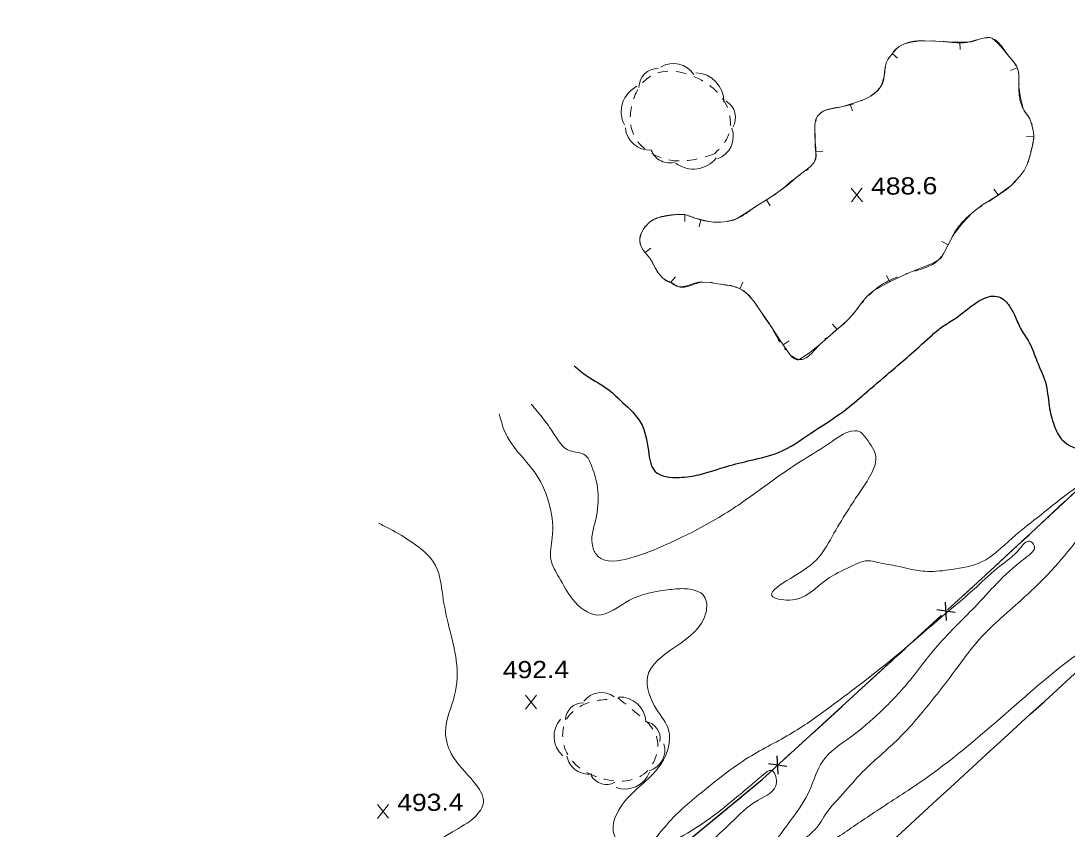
# Model space of a CAD drawing. Extents: x 2362213 to 2366494, y 6968794 to 6978110.
# Drawn here: x 2365880.2 to 2366171.9, y 6977341.8 to 6977567.2 of the extents above; entities that cross this region are included whole.
import ezdxf

# ---------------------------------------------------------------- set-up
doc = ezdxf.new("R2010")
doc.units = 0
doc.header["$LTSCALE"] = 1.9
for name, pattern in [('DOT_DASHED', [7.7, 5, -1.2, 0.3, -1.2]), ('LONG_DASH_SHORT_DASH', [9.9, 6, -1.2, 1.5, -1.2]), ('SHORT_DASHED', [2.7, 1.5, -1.2])]:
    doc.linetypes.add(name, pattern=pattern)
for name, color, linetype, lineweight in [('17', 7, 'Continuous', 25), ('2', 7, 'Continuous', 25), ('29', 7, 'Continuous', 13), ('31', 7, 'Continuous', 25), ('35', 7, 'Continuous', 13), ('37', 7, 'Continuous', 13)]:
    doc.layers.add(name, color=color, linetype=linetype, lineweight=lineweight)

msp = doc.modelspace()

# ---------------------------------------------------------------- linework, layer by layer
at = {"layer": '17'}
for p, q in [((2366140.674, 6977402.201), (2366135.606, 6977402.993)), ((2366138.314, 6977400.048), (2366137.975, 6977405.155)), ((2366092.575, 6977360.861), (2366136.841, 6977401.364)), ((2366091.391, 6977357.11), (2366091.042, 6977362.226)), ((2366093.75, 6977359.272), (2366088.681, 6977360.064))]:
    msp.add_line(p, q, dxfattribs=at)
at = {"layer": '17', "linetype": 'LONG_DASH_SHORT_DASH'}
msp.add_lwpolyline([(2365983.55, 6977264.148), (2366017.125, 6977295.339), (2366039.325, 6977316.401), (2366086.873, 6977355.657), (2366149.203, 6977412.683), (2366216.719, 6977475.439), (2366310.108, 6977562.092), (2366339.856, 6977586.717), (2366399.795, 6977631.2)], dxfattribs=at)
at = {"layer": '17'}
for points in [[(2366139.498, 6977403.8), (2366149.203, 6977412.683), (2366183.512, 6977444.571)], [(2366043.78, 6977320.084), (2366086.873, 6977355.657), (2366089.918, 6977358.436)]]:
    msp.add_lwpolyline(points, dxfattribs=at)
at = {"layer": '2'}
for points in [[(2365903.868, 6977136.953), (2366004.462, 6977229.375), (2366102.28, 6977319.291), (2366221.396, 6977428.431), (2366331.604, 6977527.895), (2366415.835, 6977603.96)], [(2366440.637, 6977561.845), (2366356.574, 6977485.121), (2366258.494, 6977395.293), (2366146.09, 6977293.258), (2366048.337, 6977203.972), (2365937.402, 6977102.032)]]:
    msp.add_spline(points, degree=3, dxfattribs=at)
at = {"layer": '29'}
for centre, radius, start, end in [((2366062.181, 6977548.703), 6.666, 32.06986, 122.06986), ((2366057.839, 6977548.637), 5.327, 89.3605, 179.3605), ((2366068.198, 6977544.775), 7.995, 358.55459, 88.55459), ((2366055.58, 6977541.86), 7.995, 116.95032, 206.95032), ((2366074.12, 6977540.307), 5.327, 329.08541, 59.08541), ((2366055.41, 6977537.869), 6.666, 184.26168, 274.26168), ((2366072.169, 6977535.049), 6.666, 289.80431, 19.80431), ((2366061.003, 6977532.969), 5.327, 199.27532, 289.27532), ((2366067.729, 6977533.893), 7.995, 232.39118, 322.39118), ((2366041.993, 6977373.864), 6.05, 53.36549, 143.36549), ((2366036.865, 6977372.204), 4.835, 88.09885, 178.09885), ((2366047.197, 6977371.422), 7.256, 3.13261, 93.13261), ((2366036.098, 6977367.728), 7.256, 138.79847, 228.79847), ((2366053.605, 6977367.054), 4.835, 350.69712, 80.69712), ((2366053.695, 6977363.928), 6.05, 286.12563, 16.12563), ((2366038.388, 6977363.234), 6.05, 189.70163, 279.70163), ((2366043.475, 6977359.107), 4.835, 208.93065, 298.93065), ((2366048.672, 6977360.262), 7.256, 249.60415, 339.60415)]:
    msp.add_arc(centre, radius, start, end, dxfattribs=at)
at = {"layer": '29', "linetype": 'SHORT_DASHED'}
for points in [[(2366073.711, 6977530.209), (2366063.66, 6977528.173), (2366051.1, 6977535.384), (2366055.684, 6977551.778), (2366069.966, 6977550.684), (2366077.652, 6977541.647), (2366077.247, 6977534.813), (2366073.67, 6977530.259)], [(2366046.635, 6977378.464), (2366052.117, 6977373.986), (2366057.459, 6977367.527), (2366054.503, 6977357.678), (2366042.199, 6977355.931), (2366032.073, 6977363.834), (2366032.145, 6977372.076), (2366037.361, 6977376.636), (2366045.618, 6977378.165)]]:
    msp.add_spline(points, degree=3, dxfattribs=at)
at = {"layer": '31', "lineweight": 13}
for p, q in [((2366114.842, 6977516.76), (2366111.725, 6977520.612)), ((2366111.762, 6977516.731), (2366114.805, 6977520.641)), ((2366023.984, 6977375.339), (2366020.866, 6977379.189)), ((2366020.903, 6977375.309), (2366023.947, 6977379.218)), ((2365982.701, 6977344.854), (2365979.586, 6977348.705)), ((2365979.623, 6977344.825), (2365982.665, 6977348.734))]:
    msp.add_line(p, q, dxfattribs=at)
at = {"layer": '31'}
msp.add_spline([(2366034.483, 6977470.993), (2366038.04, 6977468.167), (2366044.127, 6977464.324), (2366048.042, 6977460.751), (2366052.902, 6977455.388), (2366055.159, 6977447.289), (2366056.993, 6977441.646), (2366063.86, 6977439.911), (2366069.234, 6977440.662), (2366077.012, 6977442.967), (2366083.785, 6977444.701), (2366091.456, 6977446.874), (2366100.444, 6977452.24), (2366108.752, 6977457.769), (2366114.727, 6977462.607), (2366123.981, 6977470.515), (2366128.465, 6977474.368), (2366134.345, 6977479.714), (2366137.204, 6977481.981), (2366140.851, 6977484.356), (2366146.162, 6977488.367), (2366150.613, 6977490.42), (2366152.914, 6977490.271), (2366155.83, 6977487.719), (2366157.54, 6977484.615), (2366159.194, 6977480.961), (2366161.367, 6977477.512), (2366163.507, 6977472.312), (2366165.862, 6977466.474), (2366166.935, 6977459.834), (2366168.317, 6977454.408), (2366170.585, 6977450.358), (2366177.191, 6977447.731), (2366182.075, 6977449.557), (2366190.245, 6977454.696), (2366200.657, 6977463.025), (2366204.727, 6977468.354), (2366207.486, 6977473.72), (2366212.585, 6977483.179), (2366217.786, 6977488.279), (2366229.22, 6977496.428), (2366235.153, 6977500.226), (2366242.66, 6977504.807), (2366247.501, 6977505.873), (2366249.301, 6977502.751), (2366249.766, 6977500.145), (2366248.137, 6977495.868), (2366239.159, 6977484.962), (2366231.772, 6977475.262), (2366221.969, 6977465.028), (2366220.258, 6977462.931)], degree=3, dxfattribs=at)
at = {"layer": '35'}
for points in [[(2366022.463, 6977460.358), (2366025.842, 6977456.29), (2366028.63, 6977452.316), (2366033.238, 6977447.37), (2366037.55, 6977446.131), (2366039.277, 6977443.267), (2366041.075, 6977436.094), (2366040.461, 6977428.168), (2366039.624, 6977420.52), (2366041.209, 6977417.804), (2366049.864, 6977417.357), (2366060.307, 6977421.257), (2366066.41, 6977424.165), (2366079.568, 6977431.761), (2366090.307, 6977439.413), (2366097.579, 6977444.342), (2366106.476, 6977450.037), (2366112.679, 6977452.927), (2366113.61, 6977452.845), (2366115.94, 6977450.718), (2366118.579, 6977445.522), (2366116.842, 6977440.076), (2366113.905, 6977435.508), (2366111.115, 6977431.262), (2366106.9, 6977424.32), (2366102.694, 6977417.64), (2366094.77, 6977411.764), (2366089.586, 6977406.955), (2366094.468, 6977405.691), (2366104.923, 6977411.471), (2366111.58, 6977415.064), (2366117.105, 6977416.667), (2366119.379, 6977416.169), (2366124.628, 6977415.169), (2366127.896, 6977414.41), (2366132.993, 6977413.698), (2366139.809, 6977414.243), (2366148.088, 6977416.332), (2366156.576, 6977423.003), (2366163.553, 6977428.65), (2366172.386, 6977435.604), (2366178.929, 6977440.647), (2366182.262, 6977443.539), (2366187.4, 6977446.948), (2366191.377, 6977449.236), (2366191.966, 6977448.321), (2366189.019, 6977441.663), (2366187.804, 6977439.101), (2366181.754, 6977431.754), (2366173.753, 6977421.267), (2366166.611, 6977412.948), (2366159.012, 6977405.606), (2366146.87, 6977394.09), (2366140.806, 6977386.221), (2366133.9, 6977377.295), (2366124.312, 6977366.473), (2366115.619, 6977358.49), (2366110.085, 6977352.477), (2366104.488, 6977345.824), (2366100.963, 6977341.039), (2366098.119, 6977337.293), (2366098.478, 6977336.366), (2366101.937, 6977336.409), (2366108.653, 6977340.052), (2366118.859, 6977346.941), (2366131.439, 6977355.231), (2366149.435, 6977369.393), (2366161.616, 6977379.989), (2366180.529, 6977394.42), (2366186.358, 6977397.766), (2366199.886, 6977405.405), (2366210.622, 6977412.107), (2366220.878, 6977418.815), (2366228.477, 6977423.248), (2366233.166, 6977425.453), (2366236.793, 6977426.817), (2366243.377, 6977429.53), (2366250.655, 6977432.011), (2366253.973, 6977432.162), (2366257.463, 6977432.185), (2366262.578, 6977430.523), (2366264.282, 6977428.049), (2366266.206, 6977424.577), (2366266.382, 6977418.689), (2366264.391, 6977413.43), (2366261.413, 6977405.831), (2366257.476, 6977398.343), (2366250.572, 6977388.177), (2366240.063, 6977375.316), (2366229.503, 6977364.895), (2366218.841, 6977353.403), (2366209.693, 6977342.715), (2366198.055, 6977330.764), (2366188.256, 6977320.259), (2366178.313, 6977307.915), (2366164.632, 6977294.283), (2366152.223, 6977282.495)], [(2365880.182, 6977162.669), (2365882.691, 6977164.893), (2365887.056, 6977168.515), (2365893.475, 6977173.917), (2365899.091, 6977178.579), (2365905.489, 6977185.141), (2365908.161, 6977189.157), (2365913.006, 6977194.904), (2365917.148, 6977197.933), (2365920.521, 6977197.535), (2365923.026, 6977192.869), (2365926.023, 6977193.207), (2365932.717, 6977198.051), (2365944.859, 6977208.437), (2365955.882, 6977217.603), (2365970.594, 6977230.093), (2365976.985, 6977236.285), (2365987.668, 6977245.526), (2365998.863, 6977255.524), (2366009.515, 6977265.876), (2366012.174, 6977272.24), (2366014.106, 6977278.32), (2366019.63, 6977281.103), (2366022.297, 6977280.418), (2366024.586, 6977279.58), (2366027.021, 6977279.983), (2366029.101, 6977278.963), (2366033.795, 6977280.628), (2366037.91, 6977282.277), (2366041.745, 6977284.904), (2366048.493, 6977289.478), (2366053.623, 6977295.696), (2366061.627, 6977304.734), (2366066.032, 6977310.576), (2366068.335, 6977313.458), (2366075.422, 6977321.086), (2366080.862, 6977327.428), (2366088.806, 6977336.474), (2366095.327, 6977344.937), (2366100.093, 6977352.622), (2366103.765, 6977360.798), (2366111.543, 6977367.512), (2366119.776, 6977374.471), (2366128.21, 6977383.471), (2366135.069, 6977392.137), (2366146.158, 6977403.763), (2366160.23, 6977417.408), (2366162.746, 6977420.962), (2366161.505, 6977422.11), (2366158.675, 6977419.963), (2366153.179, 6977415.201), (2366146.615, 6977409.329), (2366137.937, 6977401.855), (2366125.933, 6977391.59), (2366117.509, 6977384.75), (2366106.089, 6977376.11), (2366095.291, 6977368.677), (2366083.164, 6977361.851), (2366069.889, 6977351.975), (2366059.639, 6977342.316), (2366051.152, 6977335.695), (2366045.722, 6977339.943), (2366048.59, 6977349.582), (2366058.71, 6977360.079), (2366060.791, 6977369.459), (2366057.415, 6977375.257), (2366054.919, 6977384.294), (2366071.191, 6977402.139), (2366070.747, 6977406.715), (2366065.256, 6977408.872), (2366060.528, 6977408.548), (2366049.915, 6977405.667), (2366040.855, 6977401.52), (2366034.053, 6977405.886), (2366030.284, 6977411.99), (2366027.957, 6977416.988), (2366028.359, 6977423.052), (2366027.706, 6977431.727), (2366023.892, 6977440.701), (2366015.463, 6977451.931), (2366013.538, 6977457.683)], [(2366152.223, 6977282.495), (2366137.48, 6977269.164), (2366127.401, 6977258.388), (2366118.523, 6977249.922), (2366117.96, 6977248.097), (2366119.044, 6977246.588), (2366121.484, 6977246.551), (2366126.773, 6977250.861), (2366140.883, 6977262.567), (2366156.737, 6977275.887), (2366174.131, 6977290.174), (2366190.688, 6977304.213), (2366211.305, 6977321.49), (2366231.204, 6977339.61), (2366246.965, 6977354.221), (2366270.092, 6977373.542), (2366286.124, 6977386.966), (2366306.411, 6977404.189), (2366319.943, 6977415.729), (2366336.838, 6977429.96), (2366354.441, 6977444.438), (2366361.918, 6977450.03), (2366367.772, 6977451.716), (2366372.313, 6977451.719), (2366373.898, 6977448.964), (2366372.614, 6977445.301), (2366369.195, 6977438.879), (2366363.214, 6977432.632), (2366354.604, 6977423.079), (2366342.302, 6977409.612), (2366327.29, 6977397.188), (2366311.288, 6977383.615), (2366289.667, 6977364.727), (2366279.323, 6977355.619), (2366272.319, 6977349.792), (2366258.434, 6977338.669), (2366245.681, 6977326.327), (2366235.563, 6977317.65), (2366218.37, 6977302.026), (2366206.626, 6977290.974), (2366190.041, 6977278.685), (2366181.707, 6977272.825), (2366173.374, 6977266.726), (2366161.242, 6977256.45), (2366147.282, 6977244.777), (2366139.539, 6977237.773), (2366132.064, 6977230.81), (2366121.213, 6977220.427), (2366111.765, 6977209.766), (2366107.156, 6977201.072), (2366105.674, 6977199.228)], [(2365979.938, 6977427.141), (2365983.063, 6977425.541), (2365989.229, 6977421.81), (2365995.831, 6977415.312), (2365997.791, 6977406.971), (2365999.554, 6977398.217), (2366001.595, 6977388.756), (2366001.127, 6977379.141), (2365998.583, 6977368.966), (2366000.201, 6977362.871), (2366006.617, 6977354.862), (2366009.15, 6977349.306), (2366006.908, 6977345.375), (2366000.508, 6977341.092), (2365985.993, 6977332.085), (2365981.742, 6977330.104), (2365977.662, 6977324.855), (2365975.538, 6977318.944), (2365976.625, 6977312.945), (2365973.435, 6977305.594), (2365967.146, 6977299.124), (2365965.894, 6977294.071), (2365969.263, 6977286.863), (2365971.693, 6977279.546), (2365966.079, 6977271.511), (2365961.628, 6977269.499), (2365957.289, 6977271.578), (2365952.849, 6977276.757), (2365949.5, 6977281.895), (2365947.552, 6977287.937), (2365944.719, 6977290.33), (2365940.726, 6977290.612), (2365932.588, 6977286.224), (2365925.314, 6977289.755), (2365919.493, 6977296.089), (2365911.156, 6977301.901), (2365903.542, 6977309.719), (2365892.542, 6977318.113), (2365882.657, 6977329.071)], [(2366044.302, 6977330.35), (2366047.549, 6977331.891), (2366056.184, 6977335.533), (2366065.001, 6977340.097), (2366073.12, 6977345.415), (2366079.214, 6977350.273), (2366083.431, 6977353.804), (2366087.161, 6977356.989), (2366089.42, 6977358.201), (2366090.852, 6977354.864), (2366085.778, 6977349.916), (2366078.168, 6977343.573), (2366071.963, 6977337.864), (2366067.242, 6977333.799)]]:
    msp.add_spline(points, degree=3, dxfattribs=at)
at = {"layer": '37'}
for p, q in [((2366142.048, 6977561.261), (2366142.087, 6977559.261)), ((2366123.147, 6977558.121), (2366124.65, 6977556.805)), ((2366157.967, 6977554.172), (2366156.124, 6977553.405)), ((2366111.412, 6977544.02), (2366112.03, 6977542.115)), ((2366162.619, 6977535.066), (2366160.62, 6977534.977)), ((2366101.857, 6977530.687), (2366103.845, 6977530.906)), ((2366152.694, 6977518.691), (2366151.518, 6977520.311)), ((2366088.074, 6977517.325), (2366089.121, 6977515.625)), ((2366065.351, 6977513.279), (2366065.36, 6977511.279)), ((2366069.797, 6977511.791), (2366069.295, 6977509.846)), ((2366138.746, 6977504.827), (2366136.977, 6977505.75)), ((2366054.272, 6977502.623), (2366055.841, 6977503.868)), ((2366122.483, 6977494.462), (2366121.516, 6977496.213)), ((2366061.411, 6977494.38), (2366062.747, 6977495.863)), ((2366080.61, 6977492.533), (2366081.482, 6977494.341)), ((2366107.839, 6977481.202), (2366106.514, 6977482.699)), ((2366092.77, 6977476.879), (2366094.42, 6977478.005))]:
    msp.add_line(p, q, dxfattribs=at)
for points in [[(2366061.411, 6977494.38), (2366061.926, 6977493.925), (2366062.318, 6977493.629), (2366062.962, 6977493.275), (2366063.644, 6977493.082), (2366064.464, 6977493.039), (2366065.912, 6977493.313), (2366068.076, 6977494.054), (2366069.163, 6977494.334), (2366070.252, 6977494.405), (2366072.353, 6977494.235), (2366074.456, 6977493.945), (2366078.011, 6977493.418), (2366079.746, 6977492.955), (2366081.413, 6977492.151), (2366082.814, 6977491.064), (2366084.502, 6977489.13), (2366085.952, 6977487.014), (2366087.748, 6977484.361), (2366089.544, 6977481.708), (2366091.939, 6977478.111), (2366094.373, 6977474.503), (2366094.979, 6977473.769), (2366095.544, 6977473.254), (2366095.997, 6977472.949), (2366096.679, 6977472.695), (2366097.009, 6977472.688), (2366097.308, 6977472.791), (2366100.14, 6977474.718), (2366102.938, 6977477.016), (2366106.718, 6977480.211), (2366110.387, 6977483.456), (2366112.328, 6977485.565), (2366114.946, 6977489.03), (2366116.37, 6977490.633), (2366118.026, 6977491.999), (2366122.802, 6977494.635), (2366127.74, 6977496.932), (2366131.954, 6977498.623), (2366134.067, 6977499.493), (2366136.087, 6977500.583), (2366136.88, 6977501.24), (2366140.288, 6977507.792), (2366142.758, 6977510.816), (2366145.441, 6977513.671), (2366148.022, 6977515.726), (2366152.247, 6977518.366), (2366156.29, 6977521.316), (2366158.874, 6977524.021), (2366159.94, 6977525.531), (2366160.754, 6977527.198), (2366161.589, 6977529.816), (2366162.224, 6977532.482), (2366162.425, 6977533.474), (2366162.595, 6977534.476), (2366162.63, 6977534.956), (2366162.606, 6977535.436), (2366162.455, 6977536.564), (2366162.069, 6977538.231), (2366161.504, 6977539.876), (2366161.086, 6977540.632), (2366160.296, 6977541.664), (2366159.931, 6977542.192), (2366159.666, 6977542.779), (2366158.927, 6977545.792), (2366158.488, 6977548.838), (2366158.458, 6977550.917), (2366158.458, 6977551.957), (2366158.348, 6977552.996), (2366158.172, 6977553.694), (2366157.762, 6977554.691), (2366157.174, 6977555.595), (2366156.395, 6977556.538), (2366155.606, 6977557.46), (2366153.581, 6977559.911), (2366152.49, 6977561.111), (2366151.209, 6977562.258), (2366150.957, 6977562.426), (2366150.476, 6977562.582), (2366150.095, 6977562.618), (2366149.516, 6977562.592), (2366148.956, 6977562.507), (2366147.799, 6977562.226), (2366146.084, 6977561.65), (2366145.217, 6977561.411), (2366144.328, 6977561.303), (2366141.878, 6977561.26), (2366139.418, 6977561.306), (2366136.677, 6977561.48), (2366133.945, 6977561.664), (2366130.244, 6977561.599), (2366128.407, 6977561.321), (2366126.561, 6977560.824), (2366125.128, 6977560.09), (2366124.205, 6977559.341), (2366123.018, 6977557.97), (2366121.953, 6977556.46), (2366121.482, 6977555.535), (2366121.078, 6977553.771), (2366120.775, 6977551.018), (2366120.427, 6977549.735)], [(2366120.427, 6977549.735), (2366119.738, 6977548.599), (2366118.767, 6977547.57), (2366117.141, 6977546.264), (2366116.256, 6977545.746), (2366115.309, 6977545.337), (2366112.349, 6977544.329), (2366109.377, 6977543.35), (2366106.153, 6977542.74), (2366104.557, 6977542.314), (2366103.78, 6977541.937), (2366103.015, 6977541.409), (2366102.293, 6977540.622), (2366101.89, 6977539.858), (2366101.584, 6977538.385), (2366101.669, 6977533.655), (2366101.704, 6977532.126), (2366101.956, 6977529.818), (2366101.826, 6977528.707), (2366101.326, 6977527.682), (2366100.277, 6977526.522), (2366096.763, 6977523.809), (2366093.827, 6977521.371), (2366090.799, 6977519.061), (2366088.124, 6977517.366), (2366085.439, 6977515.7), (2366082.706, 6977513.924), (2366079.923, 6977512.157), (2366078.857, 6977511.657), (2366077.141, 6977511.271), (2366075.382, 6977511.124), (2366073.272, 6977511.144), (2366071.17, 6977511.434), (2366068.213, 6977512.196), (2366065.351, 6977513.279)], [(2366065.351, 6977513.279), (2366064.091, 6977513.277), (2366062.822, 6977513.205), (2366060.375, 6977512.891), (2366057.94, 6977512.368), (2366057.282, 6977512.172), (2366056.366, 6977511.733), (2366055.482, 6977511.075), (2366054.452, 6977510.025), (2366053.81, 6977509.199), (2366053.112, 6977507.882), (2366052.765, 6977506.519), (2366052.783, 6977505.709), (2366052.899, 6977505.08), (2366053.238, 6977504.153), (2366053.736, 6977503.298), (2366054.657, 6977502.136), (2366055.568, 6977501.016), (2366057.063, 6977498.37), (2366057.866, 6977497.007), (2366058.959, 6977495.687), (2366059.634, 6977495.093), (2366060.148, 6977494.728), (2366060.942, 6977494.346), (2366061.733, 6977494.193)]]:
    msp.add_lwpolyline(points, dxfattribs=at)
at = {"layer": '37', "linetype": 'DOT_DASHED'}
for points in [[(2366061.411, 6977494.38), (2366063.644, 6977493.082), (2366070.252, 6977494.405), (2366074.456, 6977493.945), (2366081.413, 6977492.151), (2366085.952, 6977487.014), (2366089.544, 6977481.708), (2366094.373, 6977474.503), (2366097.308, 6977472.791), (2366102.938, 6977477.016), (2366110.387, 6977483.456), (2366118.026, 6977491.999), (2366127.74, 6977496.932), (2366136.087, 6977500.583), (2366140.288, 6977507.792), (2366145.441, 6977513.671), (2366156.29, 6977521.316), (2366160.754, 6977527.198), (2366162.224, 6977532.482), (2366162.595, 6977534.476), (2366162.606, 6977535.436), (2366161.504, 6977539.876), (2366159.666, 6977542.779), (2366158.488, 6977548.838), (2366158.348, 6977552.996), (2366157.174, 6977555.595), (2366155.606, 6977557.46), (2366151.209, 6977562.258), (2366148.956, 6977562.507), (2366144.328, 6977561.303), (2366139.418, 6977561.306), (2366133.945, 6977561.664), (2366126.561, 6977560.824), (2366121.953, 6977556.46), (2366119.738, 6977548.599), (2366115.309, 6977545.337), (2366109.377, 6977543.35), (2366103.015, 6977541.409), (2366101.669, 6977533.655), (2366101.326, 6977527.682), (2366096.763, 6977523.809), (2366090.799, 6977519.061), (2366085.439, 6977515.7), (2366079.923, 6977512.157), (2366075.382, 6977511.124), (2366071.17, 6977511.434), (2366065.351, 6977513.279)], [(2366065.351, 6977513.279), (2366062.822, 6977513.205), (2366057.94, 6977512.368), (2366055.482, 6977511.075), (2366052.765, 6977506.519), (2366053.736, 6977503.298), (2366055.568, 6977501.016), (2366058.959, 6977495.687), (2366061.733, 6977494.193)]]:
    msp.add_spline(points, degree=3, dxfattribs=at)

# ---------------------------------------------------------------- texts
at = {"layer": '31', "width": 1.15}
for s, p in [('488.6', (2366117.283, 6977518.723)), ('492.4', (2366014.582, 6977383.849)), ('493.4', (2365985.143, 6977346.817))]:
    msp.add_text(s, height=4.8, rotation=0.546, dxfattribs=at).set_placement(p)

doc.saveas('drawing.dxf')
